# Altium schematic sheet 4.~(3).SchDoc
size 420 x 297 mm
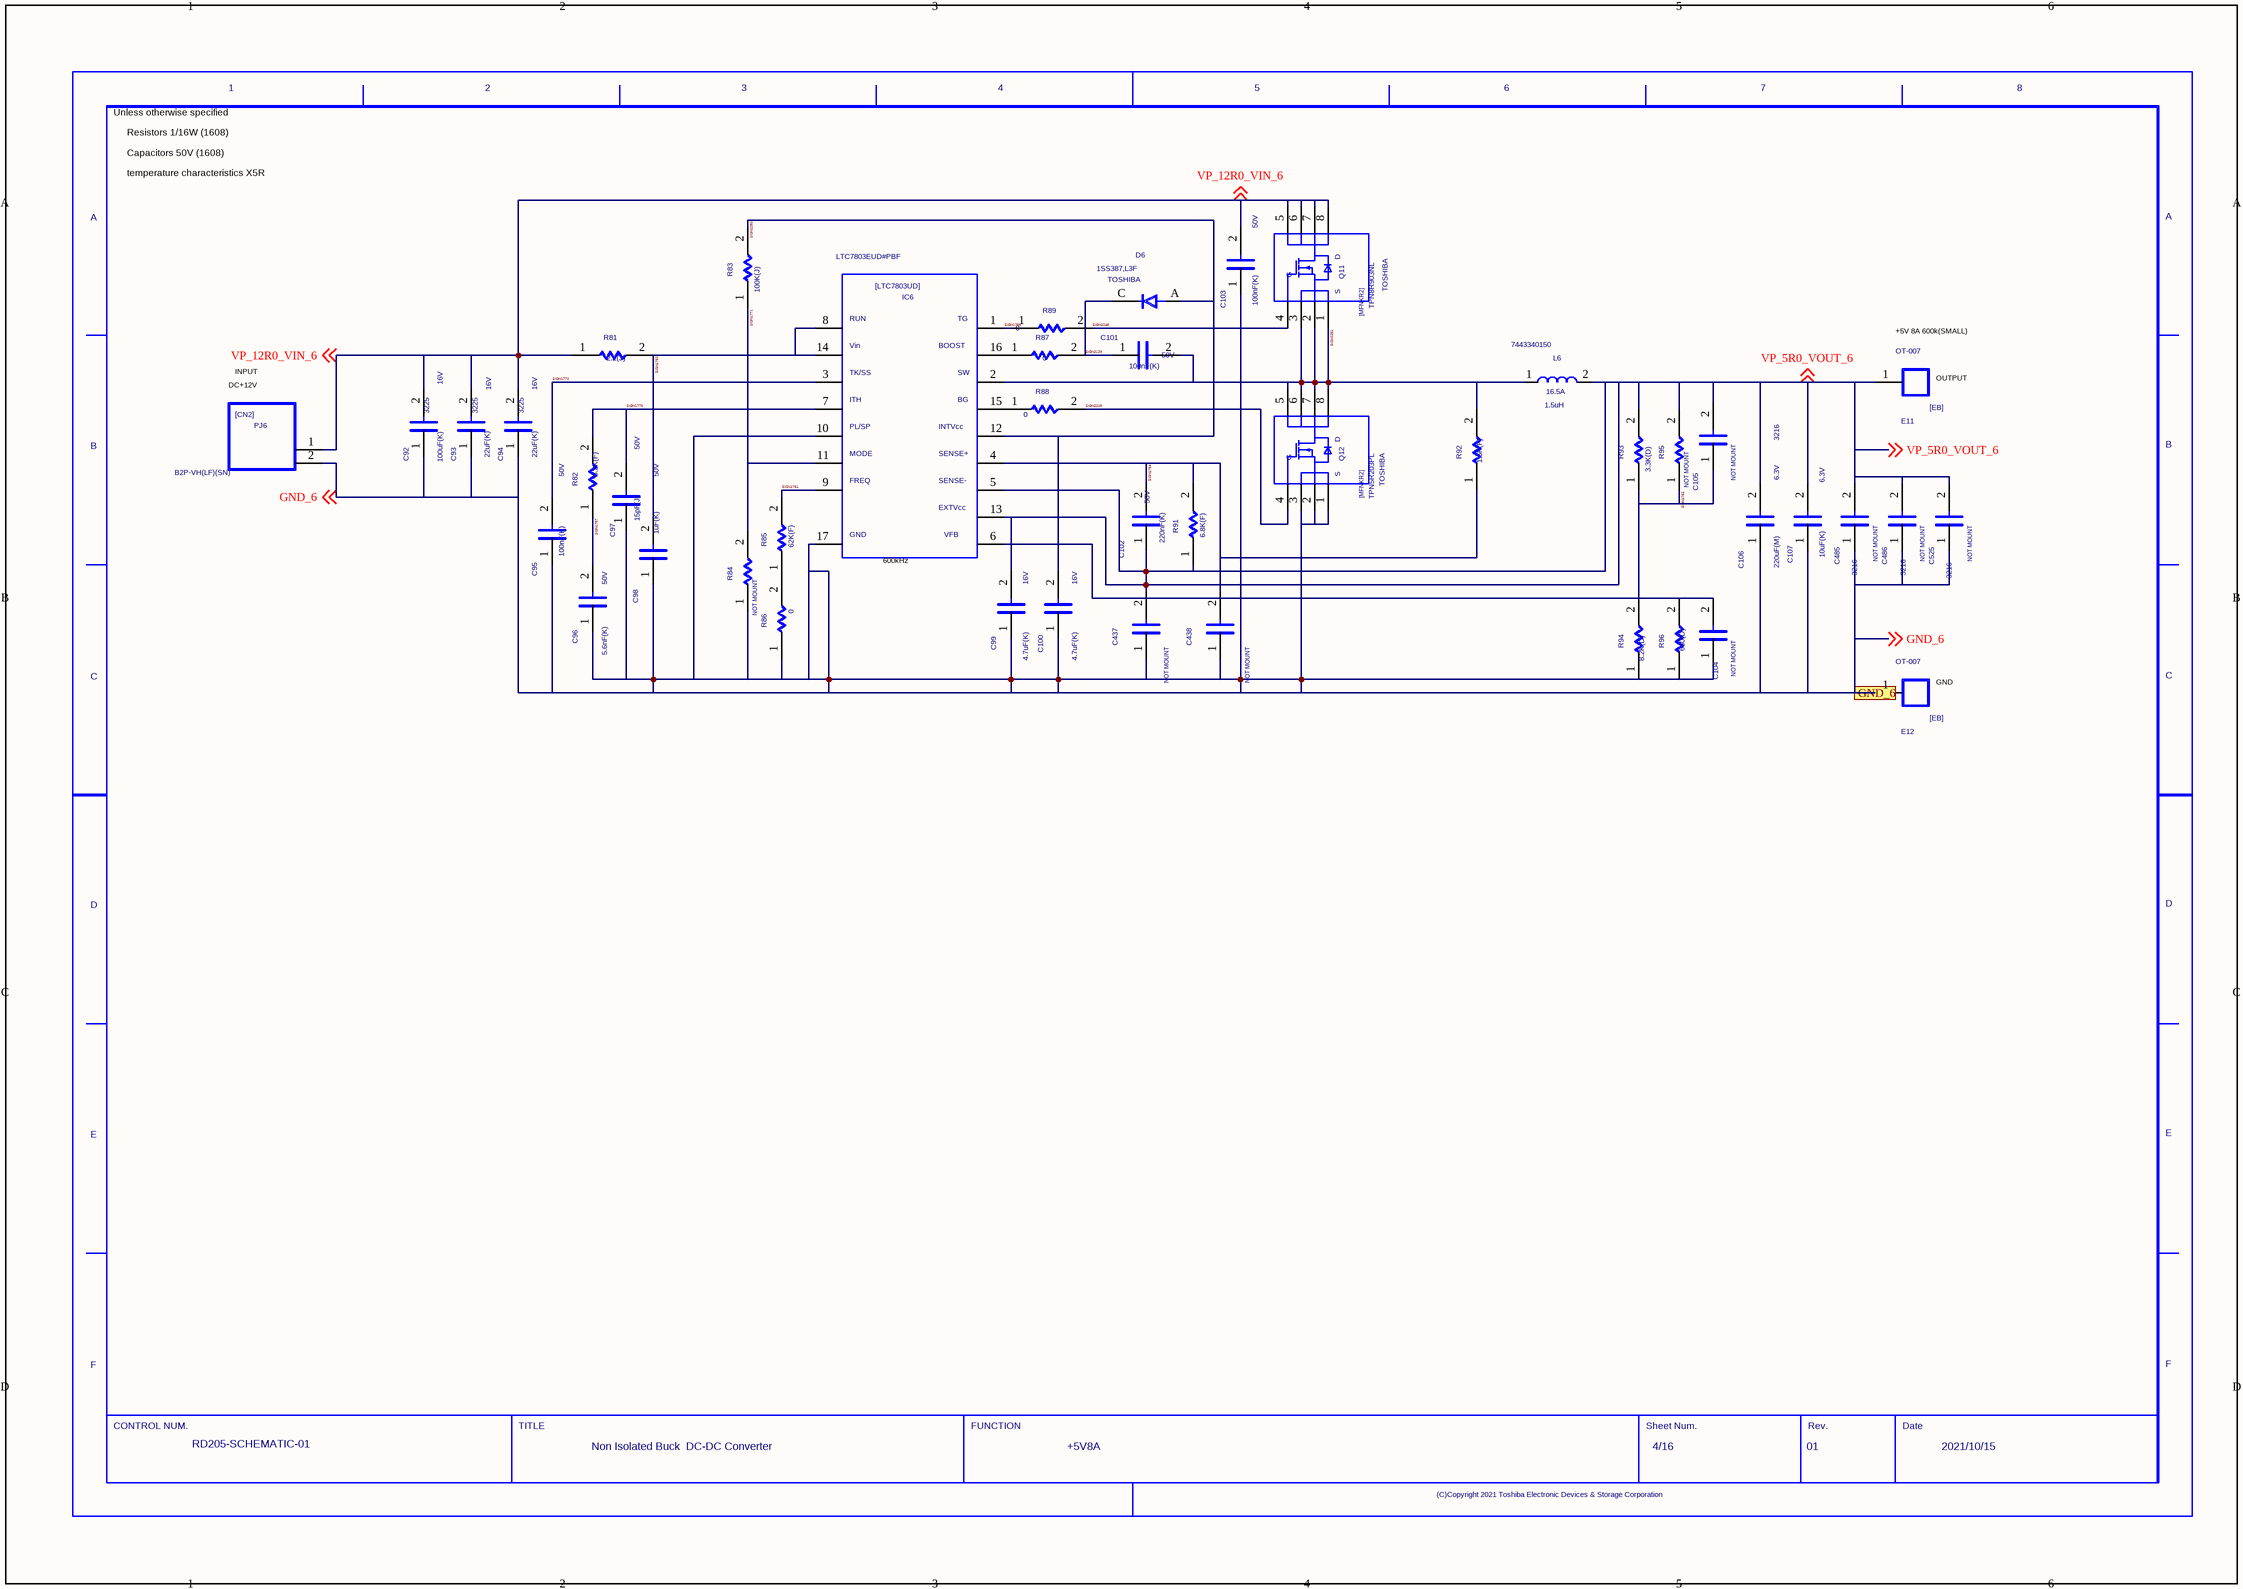
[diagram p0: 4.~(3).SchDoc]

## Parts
C92  SIZECODESMD: 3225  VAL2: 16V  VAL1: 100uF(K)  (hidden comment: C)
C93  SIZECODESMD: 3225  VAL2: 16V  VAL1: 22uF(K)  (hidden comment: C)
C94  SIZECODESMD: 3225  VAL2: 16V  VAL1: 22uF(K)  (hidden comment: C)
C95  VAL2: 50V  VAL1: 100nF(K)  (hidden comment: C)
C96  VAL2: 50V  VAL1: 5.6nF(K)  (hidden comment: C)
C97  VAL2: 50V  VAL1: 15pF(J)  (hidden comment: C)
C98  VAL2: 50V  VAL1: 1uF(K)  (hidden comment: C)
C99  VAL2: 16V  VAL1: 4.7uF(K)  (hidden comment: C)
C100  VAL2: 16V  VAL1: 4.7uF(K)  (hidden comment: C)
C101  VAL2: 50V  VAL1: 100nF(K)  (hidden comment: C)
C102  VAL2: 50V  VAL1: 220nF(K)  (hidden comment: C)
C103  VAL2: 50V  VAL1: 100nF(K)  (hidden comment: C)
C104  NOTMOUNT: NOT MOUNT  (hidden comment: C)
C105  NOTMOUNT: NOT MOUNT  (hidden comment: C)
C106  SIZECODESMD: 3216  VAL2: 6.3V  VAL1: 220uF(M)  (hidden comment: C)
C107  VAL2: 6.3V  VAL1: 10uF(K)  (hidden comment: C)
C437  NOTMOUNT: NOT MOUNT  (hidden comment: C)
C438  NOTMOUNT: NOT MOUNT  (hidden comment: C)
C485  NOTMOUNT: NOT MOUNT  SIZECODESMD: 3216  (hidden comment: C)
C486  NOTMOUNT: NOT MOUNT  SIZECODESMD: 3216  (hidden comment: C)
C525  NOTMOUNT: NOT MOUNT  SIZECODESMD: 3216  (hidden comment: C)
D6  USERCOMPTEXT3: TOSHIBA  VAL3: 1SS387,L3F  (hidden comment: D)
E11  VAL3: OT-007  (hidden comment: EB)
E12  VAL3: OT-007  (hidden comment: EB)
IC6  VAL3: LTC7803EUD#PBF  (hidden comment: LTC7803UD)
L6  VAL3: 7443340150  VAL2: 16.5A  VAL1: 1.5uH  (hidden comment: L)
PJ6  VAL3: B2P-VH(LF)(SN)  (hidden comment: CN2)
Q11  USERCOMPTEXT3: TOSHIBA  VAL3: TPN8R903NL  (hidden comment: MFNKR2)
Q12  USERCOMPTEXT3: TOSHIBA  VAL3: TPN5R203PL  (hidden comment: MFNKR2)
R81  VAL1: 2.2(J)  (hidden comment: R)
R82  VAL1: 6.2K(F)  (hidden comment: R)
R83  VAL1: 100K(J)  (hidden comment: R)
R84  NOTMOUNT: NOT MOUNT  (hidden comment: R)
R85  VAL1: 62K(F)  (hidden comment: R)
R86  VAL1: 0  (hidden comment: R)
R87  VAL1: 0  (hidden comment: R)
R88  VAL1: 0  (hidden comment: R)
R89  VAL1: 0  (hidden comment: R)
R91  VAL1: 6.8K(F)  (hidden comment: R)
R92  VAL1: 1.5K(F)  (hidden comment: R)
R93  VAL1: 3.3K(D)  (hidden comment: R)
R94  VAL1: 8.2K(D)  (hidden comment: R)
R95  NOTMOUNT: NOT MOUNT  (hidden comment: R)
R96  VAL1: 680(D)  (hidden comment: R)
U?  DATE: 2021/10/15  SHEETNUMBER: 4/16  TITLE: Non Isolated Buck / DC-DC Converter  REVISION: 01  DRAWINGNUMBER: RD205-SCHEMATIC-01  FUNCTION: +5V8A  (hidden comment: WAKU_DEF100)

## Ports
GND_6

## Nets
GND_6: C92.1 C93.1 C94.1 C95.1 C96.1 C97.1 C98.1 C99.1 C100.1 C103.1 C104.1 C106.1 C107.1 C437.1 C438.1 C485.1 C486.1 C525.1 E12.1 IC6.10 IC6.17 PJ6.2 Q12.1 Q12.2 Q12.3 R84.1 R86.1 R94.1 R96.1 ; off-sheet GND_6, port GND_6
SIGN1761: IC6.9 R85.2
SIGN1762: C104.2 C105.1 IC6.6 R93.1 R94.2 R95.1 R96.2
SIGN1763: C98.2 IC6.8 IC6.14 R81.2
SIGN1764: C102.2 C438.2 IC6.4 R91.2 R92.1
SIGN1765: IC6.1 R89.1
SIGN1767: C96.2 R82.1
SIGN1770: C97.2 IC6.7 R82.2
SIGN1771: IC6.11 R83.1 R84.2
SIGN1773: C95.2 IC6.3
SIGN2129: C101.1 D6.C R87.2
SIGN2248: Q11.4 R89.2
SIGN2249: Q12.4 R88.2
SIGN2250: C100.2 D6.A IC6.12 R83.2
SIGN2251: C101.2 IC6.2 L6.1 Q11.1 Q11.2 Q11.3 Q12.5 Q12.6 Q12.7 Q12.8 R92.2
VP_5R0_VOUT_6: C99.2 C102.1 C105.2 C106.2 C107.2 C437.2 C485.2 C486.2 C525.2 E11.1 IC6.5 IC6.13 L6.2 R91.1 R93.2 R95.2 ; off-sheet VP_5R0_VOUT_6
VP_12R0_VIN_6: C92.2 C93.2 C94.2 C103.2 PJ6.1 Q11.5 Q11.6 Q11.7 Q11.8 R81.1 ; off-sheet VP_12R0_VIN_6
NetIC6_15: IC6.15 R88.1
NetIC6_16: IC6.16 R87.1
NetR85_1: R85.1 R86.2

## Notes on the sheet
- Unless otherwise specified
- Resistors 1/16W (1608)
- Capacitors 50V (1608)
- temperature characteristics X5R
- DC+12V
- INPUT
- (near E11) +5V 8A 600k(SMALL)
- (near E11) OUTPUT
- (near IC6) 600kHz
- (near E12) GND

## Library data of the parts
C92 = C_Dup1: SQ_PART_MODEL: CON_100n; FNPARTSNAMEG: CHIP CERAMIC CAPACITOR (3225); USEINPARTSLIST: YES; OriginalSymbolOrigin: (2540,7620); MFSOLDERINGPROP: .; TEMPCHARACTERI2: B; MFFORMINGDIVP: KC; OUMECLASSIFICATION: セラミックコンデンサ; MFMOUNTSYMBOLP: 90; CDMASTERCADCELG: DC903A; PCODE: P03276001115; FNCLASSCODEG: P03-03; MAXGCOUNT: 1; RATEDVOLTAGE: 250; COMPONENTNAME: G36030160049; OUMEMAKER: KYC 京セラ; MFPACKAGEMETHOP: S; NOMINALCAPACITA: 100n; OUMEMAKERKATAMEI: CF32W5R104K250AT; CAPACITANCETOLE: K
C93 C94 = C_Dup1: SQ_PART_MODEL: CON_22u; FNPARTSNAMEG: CHIP CERAMIC CAPACITOR (3225); USEINPARTSLIST: YES; OriginalSymbolOrigin: (2540,7620); MFSOLDERINGPROP: .; TEMPCHARACTERI2: B; MFFORMINGDIVP: KC; OUMECLASSIFICATION: セラミックコンデンサ; MFMOUNTSYMBOLP: 80; CDMASTERCADCELG: DC903A; PCODE: P03043035626; FNCLASSCODEG: P03-03; MAXGCOUNT: 1; RATEDVOLTAGE: 6.3; COMPONENTNAME: G36030119054; OUMEMAKER: TYD 太陽誘電; MFPACKAGEMETHOP: S; NOMINALCAPACITA: 22u; OUMEMAKERKATAMEI: JMK325BJ226KM-T; CAPACITANCETOLE: K
C95 C101 C103 = C_Dup1: SQ_PART_MODEL: CON_100n; FNPARTSNAMEG: CHIP CERAMIC CAPACITOR (1608); USEINPARTSLIST: YES; OriginalSymbolOrigin: (2540,7620); MFSOLDERINGPROP: .; TEMPCHARACTERI2: B; MFFORMINGDIVP: KC; OUMECLASSIFICATION: セラミックコンデンサ; SIZECODESMD: 1608; MFMOUNTSYMBOLP: 80; CDMASTERCADCELG: C8100E; PCODE: P03B000000E4; FNCLASSCODEG: P03-03; MAXGCOUNT: 1; RATEDVOLTAGE: 16; COMPONENTNAME: GDM030000598; OUMEMAKER: MRT 村田製作所; MFPACKAGEMETHOP: S; NOMINALCAPACITA: 100n; OUMEMAKERKATAMEI: GRM188B11C104KA01C; CAPACITANCETOLE: K
C96 = C_Dup1: SQ_PART_MODEL: CON_5.6n; FNPARTSNAMEG: CHIP CERAMIC CAPACITOR (1608); USEINPARTSLIST: YES; OriginalSymbolOrigin: (2540,7620); TOLERANCE: K; ASIMVALUE: 5.6N; MFSOLDERINGPROP: .; TEMPCHARACTERI2: B; MFFORMINGDIVP: KC; OUMECLASSIFICATION: セラミックコンデンサ; SIZECODESMD: 1608; MFMOUNTSYMBOLP: 80; CDMASTERCADCELG: C8100E; PCODE: P03039100222; FNCLASSCODEG: P03-03; MAXGCOUNT: 1; RATEDVOLTAGE: 50; COMPONENTNAME: G36030011068; OUMEMAKER: MRT 村田製作所; MFPACKAGEMETHOP: S; OUMEMAKERKATAMEI: GRM39B562K50PT
C97 = C_Dup1: SQ_PART_MODEL: CON_15p; FNPARTSNAMEG: CHIP CERAMIC CAPACITOR (1608); USEINPARTSLIST: YES; OriginalSymbolOrigin: (2540,7620); MFSOLDERINGPROP: .; TEMPCHARACTERI2: CH; MFFORMINGDIVP: KC; OUMECLASSIFICATION: セラミックコンデンサ; SIZECODESMD: 1608; MFMOUNTSYMBOLP: 80; CDMASTERCADCELG: C8100E; PCODE: P03039230226; FNCLASSCODEG: P03-03; MAXGCOUNT: 1; RATEDVOLTAGE: 50; COMPONENTNAME: G36030104043; OUMEMAKER: MRT 村田製作所; MFPACKAGEMETHOP: S; NOMINALCAPACITA: 15p; OUMEMAKERKATAMEI: GRM39CH150J50PT; CAPACITANCETOLE: J
C98 = C_Dup1: SQ_PART_MODEL: CON_1u; FNPARTSNAMEG: CHIP CERAMIC CAPACITOR (1608); USEINPARTSLIST: YES; OriginalSymbolOrigin: (2540,7620); MFSOLDERINGPROP: .; TEMPCHARACTERI2: B; MFFORMINGDIVP: KC; OUMECLASSIFICATION: セラミックコンデンサ; SIZECODESMD: 1608; MFMOUNTSYMBOLP: 80; CDMASTERCADCELG: C8100E; PCODE: P03039ACE122; FNCLASSCODEG: P03-03; MAXGCOUNT: 1; RATEDVOLTAGE: 6.3; COMPONENTNAME: G36030104159; OUMEMAKER: KYC 京セラ; MFPACKAGEMETHOP: S; NOMINALCAPACITA: 1u; OUMEMAKERKATAMEI: CM105B105K06ATN; CAPACITANCETOLE: K
C99 = C_Dup1: SQ_PART_MODEL: CON_4.7u; FNPARTSNAMEG: CHIP CERAMIC CAPACITOR (1608); USEINPARTSLIST: YES; OriginalSymbolOrigin: (2540,7620); PCODE: P03B000000MS; MFSOLDERINGPROP: .; TEMPCHARACTERI2: B; MFFORMINGDIVP: KC; OUMECLASSIFICATION: セラミックコンデンサ; SIZECODESMD: 1608; MFMOUNTSYMBOLP: 80; CDMASTERCADCELG: C8100E; FNCLASSCODEG: P03-03; MAXGCOUNT: 1; RATEDVOLTAGE: 4; COMPONENTNAME: GDM030000053; OUMEMAKER: KYC 京セラ; MFPACKAGEMETHOP: S; NOMINALCAPACITA: 4.7u; OUMEMAKERKATAMEI: CM105B475M04AT; CAPACITANCETOLE: M
C100 = C_Dup1: SQ_PART_MODEL: CON_4.7u; FNPARTSNAMEG: CHIP CERAMIC CAPACITOR (1608); USEINPARTSLIST: YES; OriginalSymbolOrigin: (2540,7620); MFSOLDERINGPROP: .; TEMPCHARACTERI2: B; MFFORMINGDIVP: KC; OUMECLASSIFICATION: セラミックコンデンサ; SIZECODESMD: 1608; MFMOUNTSYMBOLP: 80; CDMASTERCADCELG: C8100E; PCODE: P03B000000MS; FNCLASSCODEG: P03-03; MAXGCOUNT: 1; RATEDVOLTAGE: 4; COMPONENTNAME: GDM030000053; OUMEMAKER: KYC 京セラ; MFPACKAGEMETHOP: S; NOMINALCAPACITA: 4.7u; OUMEMAKERKATAMEI: CM105B475M04AT; CAPACITANCETOLE: M
C102 = C_Dup1: SQ_PART_MODEL: CON_220n; FNPARTSNAMEG: CHIP CERAMIC CAPACITOR (1608); PARTCOMMENT: 代表セル<KC0008> がフットプリントに登録されていません。; USEINPARTSLIST: YES; OriginalSymbolOrigin: (2540,7620); MFSOLDERINGPROP: .; TEMPCHARACTERI2: B; MFFORMINGDIVP: KC; OUMECLASSIFICATION: セラミックコンデンサ; SIZECODESMD: 1608; MFMOUNTSYMBOLP: 80; CDMASTERCADCELG: KC0008; PCODE: P03B000001L3; FNCLASSCODEG: P03-03; MAXGCOUNT: 1; RATEDVOLTAGE: 16; COMPONENTNAME: GDM030001129; OUMEMAKER: MRT 村田製作所; MFPACKAGEMETHOP: S; NOMINALCAPACITA: 220n; OUMEMAKERKATAMEI: GRM188B11C224KA01D; CAPACITANCETOLE: K
C104 C105 = C_Dup1: SQ_PART_MODEL: CON_100p; FNPARTSNAMEG: CHIP CERAMIC CAPACITOR (1608); USEINPARTSLIST: YES; OriginalSymbolOrigin: (2540,7620); TOLERANCE: J; ASIMVALUE: 100P; MFSOLDERINGPROP: .; TEMPCHARACTERI2: CH; MFFORMINGDIVP: KC; OUMECLASSIFICATION: セラミックコンデンサ; SIZECODESMD: 1608; MFMOUNTSYMBOLP: 80; CDMASTERCADCELG: C8100E; PCODE: P03039177125; FNCLASSCODEG: P03-03; MAXGCOUNT: 1; RATEDVOLTAGE: 50; COMPONENTNAME: G36030011365; OUMEMAKER: KYC 京セラ; MFPACKAGEMETHOP: S; OUMEMAKERKATAMEI: CM105CH101J50AT; VAL2: 50V; VAL1: 100pF(J)
C106 = C_Dup1: SQ_PART_MODEL: CON_22u; FNPARTSNAMEG: CHIP CERAMIC CAPACITOR (3216); USEINPARTSLIST: YES; OriginalSymbolOrigin: (2540,7620); MFSOLDERINGPROP: .; TEMPCHARACTERI2: B; MFFORMINGDIVP: KC; OUMECLASSIFICATION: セラミックコンデンサ; MFMOUNTSYMBOLP: 80; CDMASTERCADCELG: DC901A; PCODE: P03B0000004V; FNCLASSCODEG: P03-03; MAXGCOUNT: 1; RATEDVOLTAGE: 6.3; COMPONENTNAME: GDM030000020; OUMEMAKER: KYC 京セラ; MFPACKAGEMETHOP: S; NOMINALCAPACITA: 22u; OUMEMAKERKATAMEI: CM316B226M06AT; CAPACITANCETOLE: M
C107 = C_Dup1: SQ_PART_MODEL: CON_1u; FNPARTSNAMEG: CHIP CERAMIC CAPACITOR (1608); PARTCOMMENT: 代表セル<KC0008> がフットプリントに登録されていません。; USEINPARTSLIST: YES; OriginalSymbolOrigin: (2540,7620); MFSOLDERINGPROP: .; TEMPCHARACTERI2: B; MFPACKAGEMETHOP: S; MFFORMINGDIVP: KC; MFMOUNTSYMBOLP: 80; PCODE: P03B000000ZQ; OUMECLASSIFICATION: セラミックコンデンサ; SIZECODESMD: 1608; CDMASTERCADCELG: KC0008; FNCLASSCODEG: P03-03; MAXGCOUNT: 1; RATEDVOLTAGE: 6.3; COMPONENTNAME: GDM030000202; OUMEMAKER: MRT 村田製作所; NOMINALCAPACITA: 1u; OUMEMAKERKATAMEI: GRM185B10J105KE21D; CAPACITANCETOLE: K
C437 C438 = C_Dup1: SQ_PART_MODEL: CON_220n; FNPARTSNAMEG: CHIP CERAMIC CAPACITOR (1608); PARTCOMMENT: 代表セル<KC0008> がフットプリントに登録されていません。; USEINPARTSLIST: YES; OriginalSymbolOrigin: (2540,7620); MFSOLDERINGPROP: .; TEMPCHARACTERI2: B; MFFORMINGDIVP: KC; OUMECLASSIFICATION: セラミックコンデンサ; SIZECODESMD: 1608; MFMOUNTSYMBOLP: 80; CDMASTERCADCELG: KC0008; PCODE: P03B000001L3; FNCLASSCODEG: P03-03; MAXGCOUNT: 1; RATEDVOLTAGE: 16; COMPONENTNAME: GDM030001129; OUMEMAKER: MRT 村田製作所; MFPACKAGEMETHOP: S; NOMINALCAPACITA: 220n; OUMEMAKERKATAMEI: GRM188B11C224KA01D; VAL2: 16V; VAL1: 220nF(K); CAPACITANCETOLE: K
C485 C486 C525 = C_Dup1: SQ_PART_MODEL: CON_22u; FNPARTSNAMEG: CHIP CERAMIC CAPACITOR (3216); USEINPARTSLIST: YES; OriginalSymbolOrigin: (2540,7620); MFSOLDERINGPROP: .; TEMPCHARACTERI2: B; MFFORMINGDIVP: KC; OUMECLASSIFICATION: セラミックコンデンサ; MFMOUNTSYMBOLP: 80; CDMASTERCADCELG: DC901A; PCODE: P03B0000004V; FNCLASSCODEG: P03-03; MAXGCOUNT: 1; RATEDVOLTAGE: 6.3; COMPONENTNAME: GDM030000020; OUMEMAKER: KYC 京セラ; MFPACKAGEMETHOP: S; NOMINALCAPACITA: 22u; OUMEMAKERKATAMEI: CM316B226M06AT; VAL2: 6.3V; VAL1: 22uF(M); CAPACITANCETOLE: M
D6 = D_Dup1: FNPARTSNAMEG: DIODE; USEINPARTSLIST: YES; PARTNAME: GDM420000143; SAVEAREA0: -565,-171,12979,8058; SAVECOUNT: 1; OriginalSymbolOrigin: (2540,5080); FORWARDVOLTAGEM: 0; MAXREVERSEVOLTA: 80; COMPONENTNAME: GDM420000143_package; MFSOLDERINGPROP: .; OUMEMAKER: TSB 東芝（ＹＰＳＳ）; QUADMODEL: dummymodel; MFPACKAGEMETHOP: S; MFFORMINGDIVP: MM; MOUNTINGFORMSMD: SMD; OUMECLASSIFICATION: 小信号ダイオード; OUMEMAKERKATAMEI: 1SS387(TPH3,F); CDMASTERCADCELG: D8101D; PCODE: P42B0000008E; FNCLASSCODEG: P42-01
E11 E12 = EB_Dup1: FNPARTSNAMEG: TERMINAL; USEINPARTSLIST: YES; PARTNAME: 5P9L1232P001; OUMEPARTTYPE: TB; OriginalSymbolOrigin: (2540,12700); COMPONENTNAME: 5P9L1232P001_package; MAXGCOUNT: 1; MFSOLDERINGPROP: .; OUMEMAKER: オサダ; QUADMODEL: dummymodel; MFPACKAGEMETHOP: I; MFFORMINGDIVP: OD; OUMECLASSIFICATION: 端子台、端子板; CDMASTERCADCELG: DE0009; KIND: PBS; PCODE: P29045001117; TERMINALSTYLE: SC; FNCLASSCODEG: P29-01
IC6 = LTC7803UD: USEINPARTSLIST: YES; SAVECOUNT: 29; SAVEAREA0: -53177,0,89020,58420; TIME: 16:14:14; UPDATEUSER: q91866sr; UPDATETIME: 13:15:36; OriginalSymbolOrigin: (5080,55880); MAXGCOUNT: 1; COMPONENTNAME: LTC7803UD_LTC7803UD; OUMEMAKER: ANALOG DEVICES
L6 = L_Dup1: USEINPARTSLIST: YES; PARTNAME: 7443340068; OriginalSymbolOrigin: (2540,5080); MAXGCOUNT: 1; COMPONENTNAME: L_L; OUMEMAKER: WURTH
PJ6 = CN2_Dup1: FNPARTSNAMEG: 3.96PITCH NYLON CONNECTOR; USEINPARTSLIST: YES; PARTNAME: G36220114012; OUMEPARTTYPE: CN; OriginalSymbolOrigin: (2540,15240); MAXGCOUNT: 1; RATEDCURRENT: 7; COMPONENTNAME: G36220114012_package; MFSOLDERINGPROP: .; OUMEMAKER: JST 日本圧着端子製造; NUMBEROFCONTACT: 2; QUADMODEL: dummymodel; MFPACKAGEMETHOP: I; MFFORMINGDIVP: CU; CONTACTPITCH: 3.96m; OUMEMAKERKATAMEI: B2P-VH; CDMASTERCADCELG: DPJ514; PCODE: P22346001114; TERMINALSTYLE: PW; FNCLASSCODEG: P22-10
Q11 Q12 = MFNKR2: USEINPARTSLIST: YES; PARTNAME: TPN1R603PL; SAVEAREA0: -9199,-39,32138,22820; TIME: 18:57:44; UPDATEUSER: q91866sr; UPDATETIME: 12:36:02; SAVECOUNT: 10; OriginalSymbolOrigin: (5080,20320); MAXGCOUNT: 1; COMPONENTNAME: MFNKR2_MFNKR2
R81 = R_Dup1: SQ_PART_MODEL: RES_2.2; FNPARTSNAMEG: CHIP RESISTOR (1608); USEINPARTSLIST: YES; OriginalSymbolOrigin: (5080,5080); TOLERANCE: J; ASIMVALUE: 2.2; MAXGCOUNT: 1; COMPONENTNAME: G36010011507; MFSOLDERINGPROP: .; OUMEMAKER: NAE 松下電子部品; MFPACKAGEMETHOP: S; MFFORMINGDIVP: KC; MOUNTINGFORMSMD: SMD; OUMECLASSIFICATION: 表面実装用固定抵抗器; MFMOUNTSYMBOLP: 80; POWERRATING: 63m; OUMEMAKERKATAMEI: ERJ3GEYJ2R2V; NUMBEROFELEMENT: 0; VAL2: 62.5mW; CDMASTERCADCELG: DR802R; PCODE: P01042157622; FNCLASSCODEG: P01-08
R82 = R_Dup1: SQ_PART_MODEL: RES_6.2K; FNPARTSNAMEG: CHIP RESISTOR (1608); USEINPARTSLIST: YES; OriginalSymbolOrigin: (5080,5080); TOLERANCE: F; ASIMVALUE: 6.2K; MAXGCOUNT: 1; COMPONENTNAME: G36010027379; MFSOLDERINGPROP: .; OUMEMAKER: KOA ＫＯＡ; MFPACKAGEMETHOP: S; MFFORMINGDIVP: KC; MOUNTINGFORMSMD: SMD; OUMECLASSIFICATION: 表面実装用固定抵抗器; MFMOUNTSYMBOLP: 80; POWERRATING: 63m; OUMEMAKERKATAMEI: RK73H1JTD6201F; NUMBEROFELEMENT: 0; VAL2: 62.5mW; CDMASTERCADCELG: DR802R; PCODE: P01042419423; FNCLASSCODEG: P01-08
R83 = R_Dup1: SQ_PART_MODEL: RES_100K; FNPARTSNAMEG: CHIP RESISTOR (1608); USEINPARTSLIST: YES; OriginalSymbolOrigin: (5080,5080); TOLERANCE: J; ASIMVALUE: 100K; MFSOLDERINGPROP: .; MFPACKAGEMETHOP: S; MFFORMINGDIVP: KC; MOUNTINGFORMSMD: SMD; MFMOUNTSYMBOLP: 80; NUMBEROFELEMENT: 0; PCODE: P01042047220; MAXGCOUNT: 1; COMPONENTNAME: G36010011057; OUMEMAKER: HDK 北陸電気工業; OUMECLASSIFICATION: 表面実装用固定抵抗器; POWERRATING: 63m; OUMEMAKERKATAMEI: CR1/16 104JV; VAL2: 62.5mW; CDMASTERCADCELG: DR802R; FNCLASSCODEG: P01-08
R84 = R_Dup1: SQ_PART_MODEL: RES_10; FNPARTSNAMEG: CHIP RESISTOR (1608); USEINPARTSLIST: YES; OriginalSymbolOrigin: (5080,5080); TOLERANCE: F; ASIMVALUE: 10; MFSOLDERINGPROP: .; MFPACKAGEMETHOP: S; MFFORMINGDIVP: KC; MOUNTINGFORMSMD: SMD; MFMOUNTSYMBOLP: 80; NUMBEROFELEMENT: 0; PCODE: P01042036620; MAXGCOUNT: 1; COMPONENTNAME: G36010104063; OUMEMAKER: NAE 松下電子部品; OUMECLASSIFICATION: 表面実装用固定抵抗器; POWERRATING: 63m; OUMEMAKERKATAMEI: ERJ3GEYF100V; VAL2: 62.5mW; VAL1: 10(F); CDMASTERCADCELG: DR802R; FNCLASSCODEG: P01-08
R85 = R_Dup1: SQ_PART_MODEL: RES_62K; FNPARTSNAMEG: CHIP RESISTOR (1608); USEINPARTSLIST: YES; OriginalSymbolOrigin: (5080,5080); MAXGCOUNT: 1; TOLERANCE: F; COMPONENTNAME: G36010027355; MFSOLDERINGPROP: .; OUMEMAKER: HDK 北陸電気工業; MFPACKAGEMETHOP: S; MFFORMINGDIVP: KC; MOUNTINGFORMSMD: SMD; OUMECLASSIFICATION: 表面実装用固定抵抗器; ASIMVALUE: 62K; MFMOUNTSYMBOLP: 80; POWERRATING: 63m; OUMEMAKERKATAMEI: CR1/16 623FV; NUMBEROFELEMENT: 0; VAL2: 62.5mW; CDMASTERCADCELG: DR802R; PCODE: P01042441226; FNCLASSCODEG: P01-08
R86 = R_Dup1: SQ_PART_MODEL: RES_10; FNPARTSNAMEG: CHIP RESISTOR (1608); USEINPARTSLIST: YES; OriginalSymbolOrigin: (5080,5080); TOLERANCE: F; ASIMVALUE: 10; MAXGCOUNT: 1; COMPONENTNAME: G36010104063; MFSOLDERINGPROP: .; OUMEMAKER: NAE 松下電子部品; MFPACKAGEMETHOP: S; MFFORMINGDIVP: KC; MOUNTINGFORMSMD: SMD; OUMECLASSIFICATION: 表面実装用固定抵抗器; MFMOUNTSYMBOLP: 80; POWERRATING: 63m; OUMEMAKERKATAMEI: ERJ3GEYF100V; VAL2: 62.5mW; CDMASTERCADCELG: DR802R; PCODE: P01042036620; FNCLASSCODEG: P01-08
R87 = R_Dup1: SQ_PART_MODEL: RES_10; FNPARTSNAMEG: CHIP RESISTOR (1608); USEINPARTSLIST: YES; OriginalSymbolOrigin: (5080,5080); TOLERANCE: F; ASIMVALUE: 10; MFSOLDERINGPROP: .; MFPACKAGEMETHOP: S; MFFORMINGDIVP: KC; MOUNTINGFORMSMD: SMD; MFMOUNTSYMBOLP: 80; PCODE: P01042036620; MAXGCOUNT: 1; COMPONENTNAME: G36010104063; OUMEMAKER: NAE 松下電子部品; OUMECLASSIFICATION: 表面実装用固定抵抗器; POWERRATING: 63m; OUMEMAKERKATAMEI: ERJ3GEYF100V; VAL2: 62.5mW; CDMASTERCADCELG: DR802R; FNCLASSCODEG: P01-08
R88 R89 = R_Dup1: SQ_PART_MODEL: RES_10; FNPARTSNAMEG: CHIP RESISTOR (2012); USEINPARTSLIST: YES; OriginalSymbolOrigin: (5080,5080); MAXGCOUNT: 1; TOLERANCE: F; COMPONENTNAME: 5P9L1083P100; MFSOLDERINGPROP: .; OUMEMAKER: 北陸電気工業; MFPACKAGEMETHOP: S; MFFORMINGDIVP: KC; MOUNTINGFORMSMD: SMD; OUMECLASSIFICATION: 表面実装用固定抵抗器; ASIMVALUE: 10; MFMOUNTSYMBOLP: 90; POWERRATING: 100m; OUMEMAKERKATAMEI: CR1/10 100FV Pb(F); VAL2: 125mW; CDMASTERCADCELG: DR910A; PCODE: P01043091222; FNCLASSCODEG: P01-08
R91 = R_Dup1: SQ_PART_MODEL: RES_6.8K; FNPARTSNAMEG: CHIP RESISTOR (1608); USEINPARTSLIST: YES; OriginalSymbolOrigin: (5080,5080); MAXGCOUNT: 1; COMPONENTNAME: G5101105R107; MFSOLDERINGPROP: .; OUMEMAKER: NAE 松下電子部品; MFPACKAGEMETHOP: S; MFFORMINGDIVP: KC; MOUNTINGFORMSMD: SMD; OUMECLASSIFICATION: 表面実装用固定抵抗器; RESISTANCETOLER: F; MFMOUNTSYMBOLP: 80; POWERRATING: 63m; OUMEMAKERKATAMEI: ERJ3GEYF682V; NOMINALRESISTAN: 6.8K; NUMBEROFELEMENT: 0; VAL2: 62.5mW; CDMASTERCADCELG: DR802R; PCODE: P01042424625; FNCLASSCODEG: P01-08
R92 = R_Dup1: SQ_PART_MODEL: RES_1.5K; FNPARTSNAMEG: CHIP RESISTOR (1608); USEINPARTSLIST: YES; OriginalSymbolOrigin: (5080,5080); TOLERANCE: F; ASIMVALUE: 1.5K; MAXGCOUNT: 1; COMPONENTNAME: G36010027232; MFSOLDERINGPROP: .; OUMEMAKER: HDK 北陸電気工業; MFPACKAGEMETHOP: S; MFFORMINGDIVP: KC; MOUNTINGFORMSMD: SMD; OUMECLASSIFICATION: 表面実装用固定抵抗器; MFMOUNTSYMBOLP: 80; POWERRATING: 63m; OUMEMAKERKATAMEI: CR1/16 152FV; NUMBEROFELEMENT: 0; VAL2: 62.5mW; CDMASTERCADCELG: DR802R; PCODE: P01042512223; FNCLASSCODEG: P01-08
R93 = R_Dup1: SQ_PART_MODEL: RES_3.3K; FNPARTSNAMEG: CHIP RESISTOR (1608); USEINPARTSLIST: YES; OriginalSymbolOrigin: (5080,5080); MAXGCOUNT: 1; COMPONENTNAME: G36010014485; MFSOLDERINGPROP: .; OUMEMAKER: SSM 進工業; MFPACKAGEMETHOP: S; MFFORMINGDIVP: KC; MOUNTINGFORMSMD: SMD; OUMECLASSIFICATION: 表面実装用固定抵抗器; RESISTANCETOLER: D; MFMOUNTSYMBOLP: 80; POWERRATING: 63m; OUMEMAKERKATAMEI: RR0816P-332-D; NOMINALRESISTAN: 3.3K; NUMBEROFELEMENT: 0; VAL2: 62.5mW; CDMASTERCADCELG: DR802R; PCODE: P01042249822; FNCLASSCODEG: P01-08
R94 = R_Dup1: ICX_PART_MODEL: RES_8.2K; FNPARTSNAMEG: CHIP RESISTOR (1608); OriginalSymbolOrigin: (5080,5080); FNCLASSCODEG: P01-08; PCODE: P01117051114; CDMASTERCADCELG: DR802R; USEWITHSCHEMA: YES; VAL2: 62.5mW; NUMBEROFELEMENT: 0; NOMINALRESISTAN: 8.2K; OUMEMAKERKATAMEI: RK73G1JTD822D; POWERRATING: 63m; MFMOUNTSYMBOLP: 80; RESISTANCETOLER: D; FUNCTION: G36010129479; OUMECLASSIFICATION: 表面実装用固定抵抗器; MOUNTINGFORMSMD: SMD; MFFORMINGDIVP: KC; MFPACKAGEMETHOP: S; OUMEMAKER: KOA ＫＯＡ; MFSOLDERINGPROP: .; MAXGCOUNT: 1
R95 = R_Dup1: SQ_PART_MODEL: RES_3.3K; FNPARTSNAMEG: CHIP RESISTOR (1608); USEINPARTSLIST: YES; OriginalSymbolOrigin: (5080,5080); TOLERANCE: F; ASIMVALUE: 3.3K; MAXGCOUNT: 1; COMPONENTNAME: G36010027027; MFSOLDERINGPROP: .; OUMEMAKER: ROH ロー・; MFPACKAGEMETHOP: S; MFFORMINGDIVP: KC; MOUNTINGFORMSMD: SMD; OUMECLASSIFICATION: 表面実装用固定抵抗器; MFMOUNTSYMBOLP: 80; POWERRATING: 63m; OUMEMAKERKATAMEI: MCR03EZPFX3301; NUMBEROFELEMENT: 0; VAL2: 62.5mW; VAL1: 3.3K(F); CDMASTERCADCELG: DR802R; PCODE: P01042250729; FNCLASSCODEG: P01-08
R96 = R_Dup1: ICX_PART_MODEL: RES_680; FNPARTSNAMEG: CHIP RESISTOR (1608); OriginalSymbolOrigin: (5080,5080); FNCLASSCODEG: P01-08; PCODE: P01117025115; CDMASTERCADCELG: DR802R; USEWITHSCHEMA: YES; VAL2: 62.5mW; NUMBEROFELEMENT: 0; NOMINALRESISTAN: 680; OUMEMAKERKATAMEI: RK73G1JTD681D; POWERRATING: 63m; MFMOUNTSYMBOLP: 80; RESISTANCETOLER: D; FUNCTION: G36010129219; OUMECLASSIFICATION: 表面実装用固定抵抗器; MOUNTINGFORMSMD: SMD; MFFORMINGDIVP: KC; MFPACKAGEMETHOP: S; OUMEMAKER: KOA ＫＯＡ; MFSOLDERINGPROP: .; MAXGCOUNT: 1
U? = WAKU_DEF100: PLOTTIME: HH:MM; SAVEAREA0: 330961,54,387907,31546; TIME: 19:23:07; UPDATEUSER: t5459927; UPDATETIME: 15:33:39; SAVECOUNT: 6; OriginalSymbolOrigin: (10160,284480); DESIGNED: ***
